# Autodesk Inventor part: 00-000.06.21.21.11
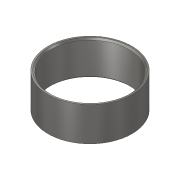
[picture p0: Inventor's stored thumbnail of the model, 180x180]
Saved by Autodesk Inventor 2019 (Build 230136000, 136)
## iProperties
Created: 2019-01
Part Number: 00-000.06.21.21.11
Material: Steel, Mild
Document SubType Name: Modeling
Designer: m.vorobev
Density: 7.85 g/cm^3
Appearance: Semi-Polished
Author: m.vorobev
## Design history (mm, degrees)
sketch "Sketch1"
  geometry: L1 (40, 17.5)-(43, 17.5); L2 (43, 17.5)-(43, -17.5); L3 (43, -17.5)-(40, -17.5); L4 (40, -17.5)-(40, 17.5); L5 (0, 0)-(2.743, 0); L6 (2.743, 0)-(2.743, 4.506); L7 (2.743, 4.506)-(0, 4.506); L8 (0, 4.506)-(0, 0); 1 further point
  constraints: 16 end point, 4 parallel, 2 horizontal, 2 perpendicular, 1 horizontal alignment, 1 midpoint
  dimensions: "D1" = 86 diameter of L2 L8; "B" = 35 distance of L1.end L2.end; "D" = 80 diameter of L4 L8
revolve "Revolution1" sketch "Sketch1" stored, may be unused: angle "d3" = 90 deg
chamfer "Chamfer1" distance "d4" = 1.5; stored, may be unused: second distance "d5" = 2, angle "d6" = 45 deg
body "Solid1"
